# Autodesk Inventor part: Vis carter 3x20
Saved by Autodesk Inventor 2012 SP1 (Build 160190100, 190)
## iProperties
Created: 2014-12
Part Number: Vis carter 3x20
Material: Default
Document SubType Name: Modeling
Designer: Bruno
Density: 1 g/cm^3
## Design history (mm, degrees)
node "Vis carter 3x201"
node "Vis carter 3x20"
node "Base1"
